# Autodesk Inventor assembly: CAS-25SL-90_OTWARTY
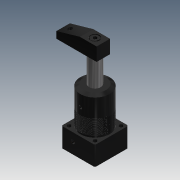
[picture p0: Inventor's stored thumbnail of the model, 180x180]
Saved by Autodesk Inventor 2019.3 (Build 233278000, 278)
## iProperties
Created: 2010-02
Part Number: CAS-25SL-90_OTWARTY
Material: Ogólny
Document SubType Name: Assembly
Designer: CADENGINEERING4
Sending System: PRO/ENGINEER BY PARAMETRIC TECHNOLOGY CORPORATION, 2007170
Preprocessor: PRO/ENGINEER BY PARAMETRIC TECHNOLOGY CORPORATION, 2007170
Title: CAS-25S_ASM
Author: Administrator
Revision Number: 2LAST_VERSION
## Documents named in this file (8)
- D:\Vault_2016\Projekty\STRONA\Pneumatic\Line ; Pipe connecct - type\cas-25s_asm\CAS-25SL-90_OTWARTY.iam
- D:\Vault_2016\Projekty\STRONA\Pneumatic\Line ; Pipe connecct - type\cas-25s_asm\CAS-25BT.ipt
- D:\Vault_2016\Projekty\STRONA\Pneumatic\Line ; Pipe connecct - type\cas-25s_asm\CAS-25SHSG.ipt
- D:\Vault_2016\Projekty\STRONA\Pneumatic\Line ; Pipe connecct - type\cas-25s_asm\CAS-25HG.ipt
- D:\Vault_2016\Projekty\STRONA\Pneumatic\Line ; Pipe connecct - type\cas-25s_asm\PRT0001M3.ipt
- D:\Vault_2016\Projekty\STRONA\Pneumatic\Line ; Pipe connecct - type\cas-25s_asm\CAS-25SYABI.ipt
- D:\Vault_2016\Projekty\STRONA\Pneumatic\Line ; Pipe connecct - type\cas-25s_asm\M6LC.ipt
- D:\Vault_2016\Projekty\STRONA\Pneumatic\Line ; Pipe connecct - type\cas-25s_asm\PRT0001.ipt
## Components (10 placed, 10 different names)
1. CAS-25BT_10
2. CAS-25SHSG_11
3. CAS-25HG_12
4. PRT0001M3_13
5. PRT0001M3_14
6. PRT0001M3_15
7. PRT0001M3_16
8. CAS-25SYABI_17
9. M6LC_18
10. PRT0001_19
